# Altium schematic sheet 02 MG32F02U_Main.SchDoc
size 299 x 210 mm
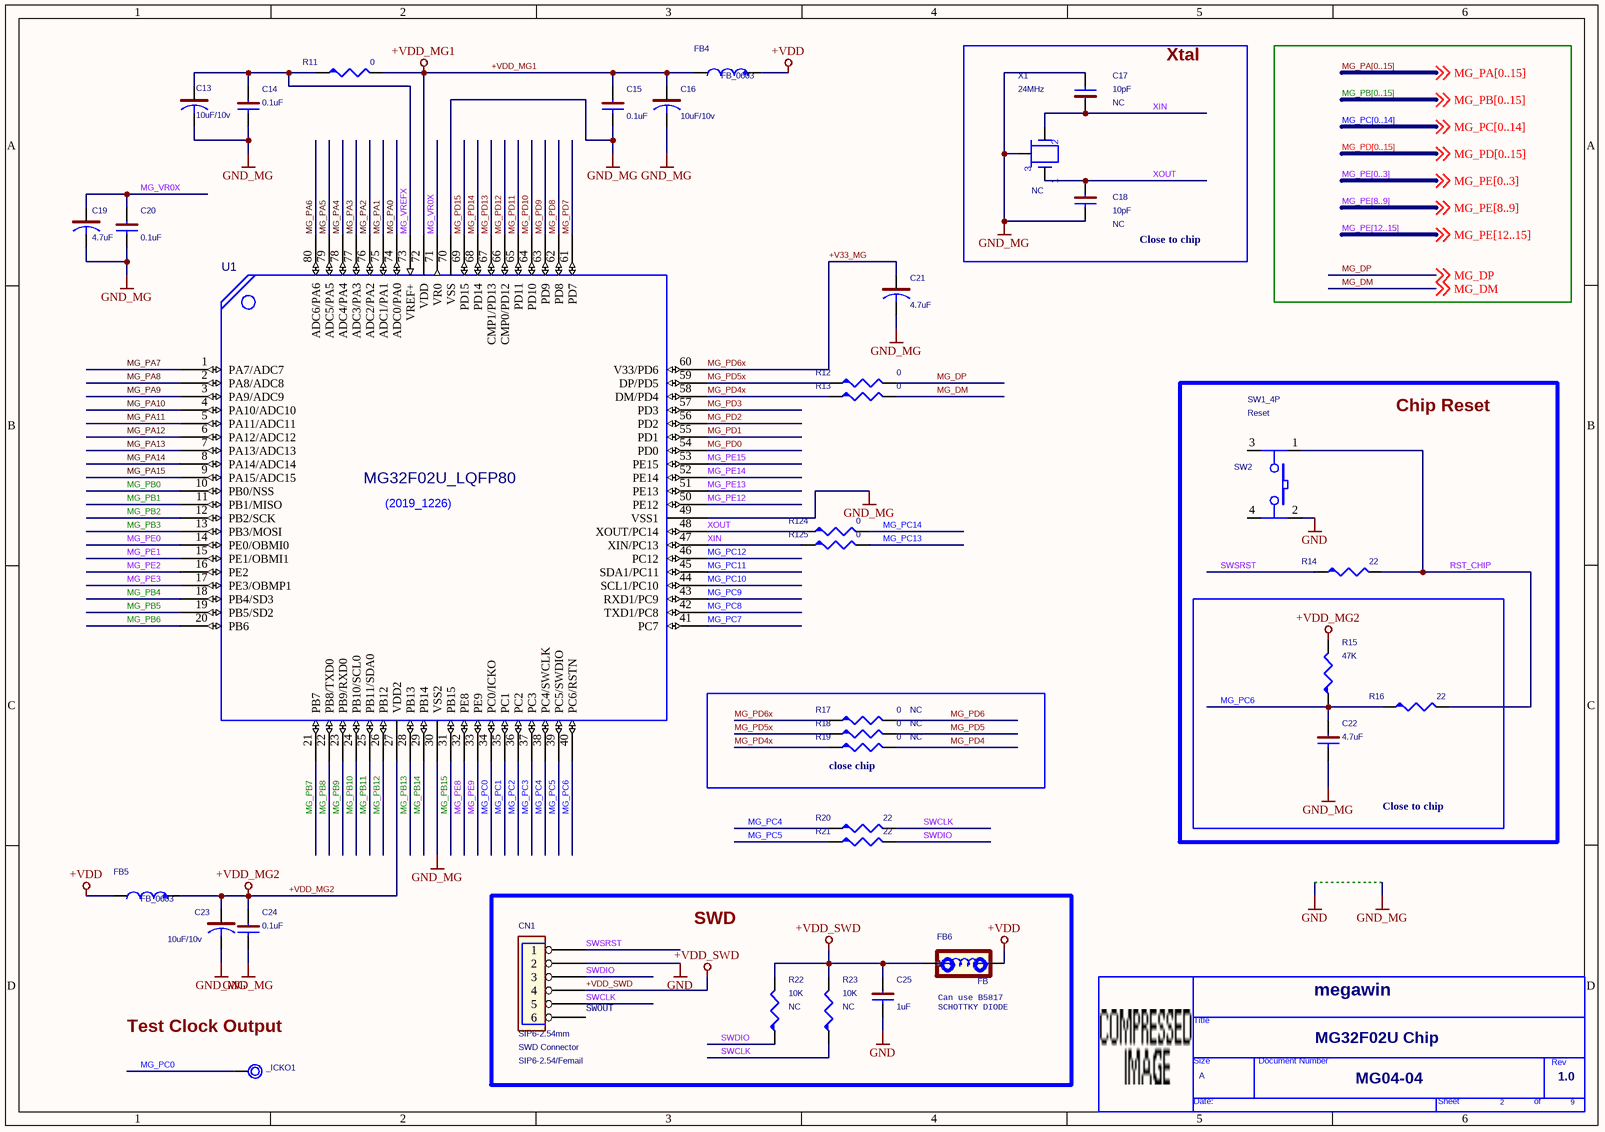
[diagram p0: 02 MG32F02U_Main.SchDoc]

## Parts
*  OrgName: megawin  Doc: MG04-04  RevCode: 1.0  Title: MG32F02U Chip  Page Size: A  Page Number: 2  Page Count: 9  (hidden comment: TitleBlock_MegaWin)  (graphical)
_ICKO1  TP-COIL  [TPH60-COIL]  (value not drawn)
C13  10uF/10v  [C-0805]
C14  0.1uF  [C-0603]
C15  0.1uF  [C-0603]
C16  10uF/10v  [C-0805]
C17  10pF  Assembly: NC  [C-0603]
C18  10pF  Assembly: NC  [C-0603]
C19  4.7uF  [C-0805]
C20  0.1uF  [C-0603]
C21  4.7uF  [C-0805]
C22  4.7uF  [C-0603]
C23  10uF/10v  [C-0805]
C24  0.1uF  [C-0603]
C25  1uF  [C-0603]
CN1  SIP6-2.54mm  Function: SWD Connector  Package: SIP6-2.54/Femail  [HD6-P2.54-UL]
FB4  FB_0603  [L-0603]
FB5  FB_0603  [L-0603]
FB6  FB  [L0805+DIP]
R11  0  [R-0603]
R12  0  [R-0603]
R13  0  [R-0603]
R14  22  [R-0603]
R15  47K  [R-0603]
R16  22  [R-0603]
R17  0  Assembly: NC  [R-0603]
R18  0  Assembly: NC  [R-0603]
R19  0  Assembly: NC  [R-0603]
R20  22  [R-0603]
R21  22  [R-0603]
R22  10K  Assembly: NC  [R-0603]
R23  10K  Assembly: NC  [R-0603]
R124  0  [R-0603]
R125  0  [R-0603]
SW2  SW1_4P  Function: Reset  [SW-TACT-P4.5X6.5-Z6.2X6.2X5]
U1  MG32F02U_LQFP80  [QFP80-P0.4-Z12X12]
X1  24MHz  Assembly: NC  [XTAL-HC49US-G2]

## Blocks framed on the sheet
Xtal: C17 C18 X1
Chip Reset: R14 SW2
Close to chip: C22 R15 R16
close chip: R17-R19
SWD: C25 CN1 FB6 R22 R23

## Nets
+VDD: FB4.1 FB5.2 FB6.2
+VDD_MG1: C15.1 C16.1 FB4.2 R11.2 U1.72(VDD)
+VDD_MG2: C23.1 C24.1 FB5.1 R15.2 U1.27(VDD2)
+VDD_SWD: C25.1 CN1.4 FB6.1 R22.2 R23.2
GND: C25.2 CN1.2 SW2.2
GND_MG: C13.2 C14.2 C15.2 C16.2 C17.2 C18.2 C19.2 C20.2 C21.2 C22.2 C23.2 C24.2 U1.30(VSS2) U1.49(VSS1) U1.70(VSS) X1.3
+V33_MG: C21.1 R17.1 U1.60(V33/PD6)  [also labelled MG_PD6x]
MG_DM: R13.2 ; off-sheet MG_DM
MG_DP: R12.2 ; off-sheet MG_DP
MG_PA0: U1.74(ADC0/PA0)
MG_PA1: U1.75(ADC1/PA1)
MG_PA2: U1.76(ADC2/PA2)
MG_PA3: U1.77(ADC3/PA3)
MG_PA4: U1.78(ADC4/PA4)
MG_PA5: U1.79(ADC5/PA5)
MG_PA6: U1.80(ADC6/PA6)
MG_PA7: U1.1(PA7/ADC7)
MG_PA8: U1.2(PA8/ADC8)
MG_PA9: U1.3(PA9/ADC9)
MG_PA10: U1.4(PA10/ADC10)
MG_PA11: U1.5(PA11/ADC11)
MG_PA12: U1.6(PA12/ADC12)
MG_PA13: U1.7(PA13/ADC13)
MG_PA14: U1.8(PA14/ADC14)
MG_PA15: U1.9(PA15/ADC15)
MG_PB0: U1.10(PB0/NSS)
MG_PB1: U1.11(PB1/MISO)
MG_PB2: U1.12(PB2/SCK)
MG_PB3: U1.13(PB3/MOSI)
MG_PB4: U1.18(PB4/SD3)
MG_PB5: U1.19(PB5/SD2)
MG_PB6: U1.20(PB6)
MG_PB7: U1.21(PB7)
MG_PB8: U1.22(PB8/TXD0)
MG_PB9: U1.23(PB9/RXD0)
MG_PB10: U1.24(PB10/SCL0)
MG_PB11: U1.25(PB11/SDA0)
MG_PB12: U1.26(PB12)
MG_PB13: U1.28(PB13)
MG_PB14: U1.29(PB14)
MG_PB15: U1.31(PB15)
MG_PC0: _ICKO1.1 U1.34(PC0/ICKO)
MG_PC1: U1.35(PC1)
MG_PC2: U1.36(PC2)
MG_PC3: U1.37(PC3)
MG_PC4: R20.1 U1.38(PC4/SWCLK)
MG_PC5: R21.1 U1.39(PC5/SWDIO)
MG_PC6: C22.1 R15.1 R16.1 U1.40(PC6/RSTN)
MG_PC7: U1.41(PC7)
MG_PC8: U1.42(TXD1/PC8)
MG_PC9: U1.43(RXD1/PC9)
MG_PC10: U1.44(SCL1/PC10)
MG_PC11: U1.45(SDA1/PC11)
MG_PC12: U1.46(PC12)
MG_PC13: R125.2
MG_PC14: R124.2
MG_PD0: U1.54(PD0)
MG_PD1: U1.55(PD1)
MG_PD2: U1.56(PD2)
MG_PD3: U1.57(PD3)
MG_PD4: R19.2
MG_PD4x: R13.1 R19.1 U1.58(DM/PD4)
MG_PD5: R18.2
MG_PD5x: R12.1 R18.1 U1.59(DP/PD5)
MG_PD6: R17.2
MG_PD7: U1.61(PD7)
MG_PD8: U1.62(PD8)
MG_PD9: U1.63(PD9)
MG_PD10: U1.64(PD10)
MG_PD11: U1.65(PD11)
MG_PD12: U1.66(CMP0/PD12)
MG_PD13: U1.67(CMP1/PD13)
MG_PD14: U1.68(PD14)
MG_PD15: U1.69(PD15)
MG_PE0: U1.14(PE0/OBMI0)
MG_PE1: U1.15(PE1/OBMI1)
MG_PE2: U1.16(PE2)
MG_PE3: U1.17(PE3/OBMP1)
MG_PE8: U1.32(PE8)
MG_PE9: U1.33(PE9)
MG_PE12: U1.50(PE12)
MG_PE13: U1.51(PE13)
MG_PE14: U1.52(PE14)
MG_PE15: U1.53(PE15)
MG_VR0X: C19.1 C20.1 U1.71(VR0)
MG_VREFX: C13.1 C14.1 R11.1 U1.73(VREF+)
RST_CHIP: R14.2 R16.2 SW2.1
SWCLK: CN1.5 R20.2 R23.1
SWDIO: CN1.3 R21.2 R22.1
SWSRST: CN1.1 R14.1
XIN: C17.1 R125.1 U1.47(XIN/PC13) X1.2
XOUT: C18.1 R124.1 U1.48(XOUT/PC14) X1.1

Not connected (* = marked no-connect by the designer): CN1 6; SW2 3 4

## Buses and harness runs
bus MG_PA[0..15]
bus MG_PB[0..15]
bus MG_PC[0..14]
bus MG_PD[0..15]
bus MG_PE[0..3]
bus MG_PE[8..9]
bus MG_PE[12..15]

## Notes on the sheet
- Close to chip
- (near CN1) SWOUT
- (near FB6) Can use B5817
  SCHOTTKY DIODE
- (near _ICKO1) Test Clock Output

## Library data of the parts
_ICKO1 = TPH60-COIL: Assembly: NC
C13 C16 C19 C21 C23 = CAP-POL
C14 C15 C17 C18 C20 C22 C24 C25 = CAP-NP
CN1 = SIP6
FB4 FB5 = FB2
FB6 = FB+DIP
R11-R13 R17-R21 R124 R125 = R: 2ND PART FIELD: SMD_0805
R14-R16 R22 R23 = R
SW2 = SW-PB-4P
U1 = IC-MG32F02U128-LQFP80: Designator: A; OriginalSymbolOrigin: (0,0); SWAP_INFO: (S1+S2); SPLIT_INST: TRUE
X1 = XTAL-G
